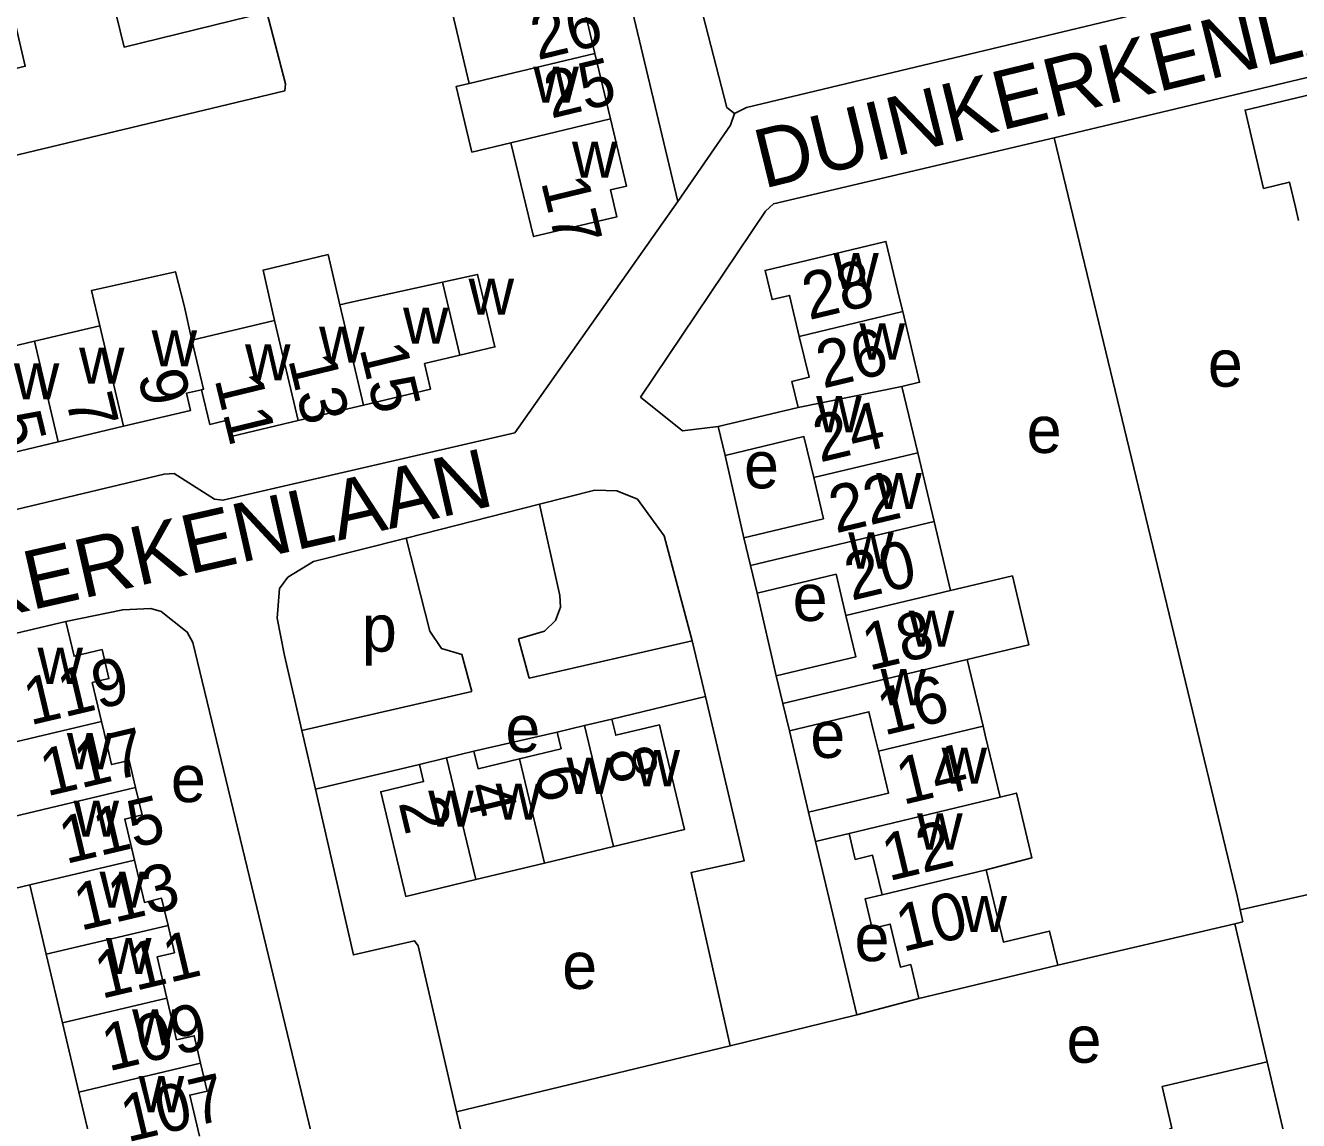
# Model space of a CAD drawing. Extents: x 157768 to 159790, y 387230 to 389604.
# Drawn here: x 159326.8 to 159435.1, y 388717.2 to 388810.4 of the extents above; entities that cross this region are included whole.
import ezdxf

# ---------------------------------------------------------------- set-up
doc = ezdxf.new("R2010")
doc.units = 0
for name, color, linetype in [('BLT_Basislijn', 7, 'Continuous'), ('BLT_Bebouwing', 7, 'Continuous'), ('BLT_Centroide', 7, 'Continuous'), ('BLT_Huisnummer', 7, 'Continuous'), ('BLT_Huisnummer_ tussenligend', 7, 'Continuous'), ('BLT_Onderverdeling_panden', 7, 'Continuous'), ('BLT_Straatnaam', 7, 'Continuous')]:
    doc.layers.add(name, color=color, linetype=linetype)

msp = doc.modelspace()

# ---------------------------------------------------------------- linework, layer by layer
at = {"layer": 'BLT_Basislijn'}
for p, q in [((159386.32, 388773.81), (159387.92, 388766.8)), ((159370.52, 388769.66), (159375.24, 388770.86)), ((159359.2, 388766.78), (159370.52, 388769.66)), ((159389.04, 388762.1), (159390.67, 388755.05)), ((159369.66, 388754.85), (159383.52, 388758.04)), ((159350.31, 388750.41), (159364.78, 388753.73)), ((159376.68, 388751.38), (159384.64, 388753.29)), ((159351.46, 388745.41), (159350.31, 388750.41)), ((159364.94, 388748.64), (159372.03, 388750.27)), ((159391.79, 388750.39), (159393.43, 388743.45)), ((159360.32, 388747.53), (159351.46, 388745.41)), ((159394.02, 388740.96), (159397.53, 388726.22)), ((159430.15, 388735.16), (159440.25, 388737.44)), ((159430.15, 388735.16), (159430.37, 388734.13)), ((159429.68, 388733.97), (159414.63, 388730.44)), ((159430.37, 388734.13), (159429.68, 388733.97)), ((159432.43, 388722.23), (159429.68, 388733.97)), ((159397.53, 388726.22), (159402.81, 388727.61)), ((159363.47, 388717.97), (159386.76, 388723.59))]:
    msp.add_line(p, q, dxfattribs=at)
for points in [[(159357.28, 388833.94), (159362.62, 388835.29), (159363.05, 388834.27), (159367.09, 388817.24), (159367.94, 388816.95), (159376.06, 388818.59), (159376.79, 388818.48), (159382.3, 388795.4)], [(159346.54, 388831.4), (159330.57, 388827.44), (159335.18, 388808.55), (159347.33, 388811.52), (159348.93, 388805.43), (159348.85, 388804.82), (159311.09, 388795.78), (159309.81, 388802.64), (159326.78, 388806.92), (159321.81, 388828.26)], [(159436.83, 388828.79), (159439.83, 388815.8), (159388.13, 388803.42), (159387.13, 388802.91)], [(159381.44, 388822.9), (159386.47, 388803.4), (159387.13, 388802.91)], [(159414.33, 388800.82), (159443.7, 388807.83), (159444.14, 388807.81), (159450.82, 388803.13), (159451.67, 388800.59), (159462.43, 388753.63), (159459.51, 388743.67), (159459.59, 388742.95)], [(159387.13, 388802.91), (159386.79, 388801.89), (159382.3, 388795.4)], [(159379.13, 388778.78), (159389.77, 388794.6), (159390.45, 388795.21), (159414.33, 388800.82)], [(159414.33, 388800.82), (159429.9, 388736.34), (159430.15, 388735.16)], [(159307.79, 388764.87), (159338.59, 388772.22), (159339.45, 388772.26), (159342.87, 388770.08), (159343.59, 388770), (159368.42, 388775.73), (159382.3, 388795.4)], [(159379.13, 388778.78), (159382.71, 388775.9), (159385.73, 388776.27)], [(159375.24, 388770.86), (159377.11, 388770.79), (159378.86, 388770.09), (159381.14, 388766.98), (159383.52, 388758.04)], [(159369.66, 388754.85), (159368.75, 388758.2), (159370.95, 388758.85), (159371.9, 388759.78), (159372.32, 388760.89), (159372.27, 388761.9), (159370.52, 388769.66)], [(159350.31, 388750.41), (159348.84, 388756.8), (159348.2, 388759.97), (159348.41, 388762.48), (159349.11, 388763.44), (159351.29, 388764.78), (159359.2, 388766.78)], [(159364.78, 388753.73), (159363.92, 388756.88), (159362.18, 388757.38), (159361.21, 388758.86), (159359.2, 388766.78)], [(159357.95, 388687.92), (159341.04, 388757.9), (159340.56, 388758.78), (159338.35, 388760.54), (159337.46, 388760.78), (159335.07, 388760.68), (159330.24, 388759.68)], [(159383.52, 388758.04), (159384.64, 388753.29)], [(159384.64, 388753.29), (159387.93, 388739.31), (159383.43, 388738.32), (159386.76, 388723.59)], [(159363.47, 388717.97), (159360.2, 388732.1), (159359.89, 388732.53), (159354.7, 388731.32), (159351.46, 388745.41)], [(159397.53, 388726.22), (159397.3, 388726.16), (159386.76, 388723.59)], [(159363.47, 388717.97), (159369.31, 388693.28), (159369.85, 388692.48), (159375.75, 388688.69), (159384.77, 388690.71)]]:
    msp.add_lwpolyline(points, dxfattribs=at)
at = {"layer": 'BLT_Bebouwing'}
for p, q in [((159376.57, 388802.43), (159375.25, 388807.99)), ((159340.96, 388783.62), (159347.99, 388785.29)), ((159327.57, 388783.53), (159333.12, 388784.84)), ((159322.02, 388782.21), (159327.57, 388783.53)), ((159401.36, 388779.67), (159402.71, 388774.03)), ((159350.01, 388776.77), (159355.57, 388778.09)), ((159392.54, 388777.9), (159385.73, 388776.27)), ((159329.59, 388774.97), (159335.14, 388776.29)), ((159385.73, 388776.27), (159386.32, 388773.81)), ((159324.04, 388773.65), (159329.59, 388774.97)), ((159402.71, 388774.03), (159404.11, 388768.19)), ((159404.11, 388768.19), (159405.51, 388762.32)), ((159387.92, 388766.8), (159388.48, 388764.45)), ((159388.48, 388764.45), (159389.04, 388762.1)), ((159323.23, 388758.02), (159330.24, 388759.68)), ((159406.92, 388756.45), (159408.27, 388750.78)), ((159390.67, 388755.05), (159391.23, 388752.72)), ((159391.23, 388752.72), (159391.79, 388750.39)), ((159374.36, 388750.83), (159372.03, 388750.27)), ((159376.68, 388751.38), (159374.36, 388750.83)), ((159364.94, 388748.64), (159362.63, 388748.09)), ((159362.63, 388748.09), (159360.32, 388747.53)), ((159393.43, 388743.45), (159394.02, 388740.96)), ((159394.02, 388740.96), (159396.88, 388741.65)), ((159370.96, 388739.13), (159376.82, 388740.53)), ((159365.11, 388737.73), (159370.96, 388739.13)), ((159327.17, 388737.28), (159328.57, 388731.37)), ((159328.57, 388731.37), (159329.95, 388725.53)), ((159329.95, 388725.53), (159331.34, 388719.65)), ((159331.34, 388719.65), (159332.72, 388713.79))]:
    msp.add_line(p, q, dxfattribs=at)
for points in [[(159375.25, 388807.99), (159373.42, 388815.68), (159362.74, 388813.14), (159364.56, 388805.45)], [(159364.56, 388805.45), (159363.43, 388805.18), (159364.78, 388799.62), (159368.09, 388800.41)], [(159443.96, 388795.9), (159443.13, 388799.41), (159444.59, 388799.76), (159444.01, 388802.23), (159439.7, 388801.21), (159438.76, 388805.14), (159430.56, 388803.19), (159432.14, 388796.52), (159434.34, 388797.05), (159434.85, 388794.92), (159435.11, 388793.8)], [(159368.09, 388800.41), (159370.03, 388792.42), (159377.1, 388794.1), (159376.56, 388796.39), (159377.93, 388796.71), (159376.57, 388802.43)], [(159401.43, 388786.04), (159401.17, 388787.15), (159400.01, 388792.01), (159389.72, 388789.55), (159390.32, 388787.06), (159391.8, 388787.42), (159392.63, 388783.94)], [(159347.99, 388785.29), (159347.01, 388789.57), (159352.55, 388790.89), (159353.55, 388786.61)], [(159333.12, 388784.84), (159332.42, 388787.84), (159339.55, 388789.44), (159340.3, 388786.55), (159340.96, 388783.62)], [(159353.55, 388786.61), (159354.38, 388786.81), (159362.28, 388788.55)], [(159362.28, 388788.55), (159365.26, 388789.21), (159366.73, 388783.04), (159363.76, 388782.33)], [(159401.43, 388786.04), (159402.87, 388780.03), (159401.36, 388779.67)], [(159392.63, 388783.94), (159393.46, 388780.46), (159392.01, 388780.11), (159392.54, 388777.9)], [(159363.76, 388782.33), (159360.76, 388781.62), (159361.27, 388779.45), (159355.57, 388778.09)], [(159335.14, 388776.29), (159340.84, 388777.64), (159340.49, 388779.1), (159341.77, 388779.4)], [(159341.77, 388779.4), (159342.47, 388776.45), (159343.97, 388776.81), (159344.3, 388775.42), (159350.01, 388776.77)], [(159386.32, 388773.81), (159393.02, 388775.41), (159393.86, 388771.92)], [(159393.86, 388771.92), (159394.69, 388768.42), (159387.92, 388766.8)], [(159389.04, 388762.1), (159395.76, 388763.7), (159396.6, 388760.18)], [(159405.51, 388762.32), (159410.76, 388763.56), (159412.15, 388757.69), (159406.92, 388756.45)], [(159330.24, 388759.68), (159330.93, 388756.72), (159333.31, 388757.29), (159333.9, 388754.83), (159332.48, 388754.49), (159333.26, 388751.18)], [(159396.6, 388760.18), (159397.44, 388756.67), (159390.67, 388755.05)], [(159391.79, 388750.39), (159398.56, 388752.01), (159399.04, 388750), (159399.37, 388748.65)], [(159333.26, 388751.18), (159333.48, 388750.25), (159334.13, 388747.51), (159335.62, 388747.86), (159336.17, 388745.55)], [(159376.82, 388740.53), (159382.86, 388741.98), (159380.94, 388750), (159380.73, 388750.89), (159377.02, 388750), (159376.68, 388751.38)], [(159408.27, 388750.78), (159408.46, 388750), (159409.71, 388744.75)], [(159372.03, 388750.27), (159372.37, 388748.86), (159368.83, 388748.01)], [(159368.83, 388748.01), (159365.3, 388747.16), (159364.94, 388748.64)], [(159399.37, 388748.65), (159400.22, 388745.07), (159393.43, 388743.45)], [(159360.32, 388747.53), (159360.67, 388746.07), (159357.02, 388745.2), (159359.15, 388736.3), (159365.11, 388737.73)], [(159336.06, 388739.39), (159335.24, 388742.88), (159336.72, 388743.23), (159336.17, 388745.55)], [(159409.71, 388744.75), (159411.11, 388745.08), (159412.42, 388739.58), (159408.53, 388738.55)], [(159325.8, 388743.09), (159325.87, 388742.8), (159321.92, 388741.87), (159323.22, 388736.34), (159327.17, 388737.28)], [(159396.88, 388741.65), (159397.4, 388739.44), (159398.87, 388739.8), (159399.67, 388736.43)], [(159338.93, 388733.82), (159338.38, 388736.14), (159336.91, 388735.79), (159336.06, 388739.39)], [(159408.53, 388738.55), (159410, 388732.41), (159413.93, 388733.35), (159414.63, 388730.44)], [(159399.67, 388736.43), (159398.23, 388736.09), (159398.83, 388733.58), (159400.36, 388733.94), (159401.24, 388730.29), (159402.12, 388730.5), (159402.81, 388727.61)], [(159338.82, 388727.63), (159337.99, 388731.15), (159339.47, 388731.5), (159338.93, 388733.82)], [(159402.81, 388727.61), (159414.63, 388730.44)], [(159341.7, 388722.1), (159341.15, 388724.45), (159339.65, 388724.1), (159338.82, 388727.63)], [(159341.6, 388715.89), (159340.77, 388719.39), (159342.26, 388719.74), (159341.7, 388722.1)], [(159424.14, 388716.53), (159424.32, 388716.57), (159423.52, 388720.14), (159432.43, 388722.23)], [(159432.43, 388722.23), (159433.96, 388715.71), (159435.1, 388710.84)]]:
    msp.add_lwpolyline(points, dxfattribs=at)
at = {"layer": 'BLT_Onderverdeling_panden'}
for p, q in [((159364.56, 388805.45), (159375.25, 388807.99)), ((159362.28, 388788.55), (159363.76, 388782.33)), ((159355.57, 388778.09), (159353.55, 388786.61)), ((159350.01, 388776.77), (159347.99, 388785.29)), ((159392.63, 388783.94), (159401.43, 388786.04)), ((159335.14, 388776.29), (159333.12, 388784.84)), ((159329.59, 388774.97), (159327.57, 388783.53)), ((159392.54, 388777.9), (159401.36, 388779.67)), ((159393.86, 388771.92), (159402.71, 388774.03)), ((159388.48, 388764.45), (159404.11, 388768.19)), ((159396.6, 388760.18), (159405.51, 388762.32)), ((159391.23, 388752.72), (159406.92, 388756.45)), ((159333.26, 388751.18), (159324.38, 388749.08)), ((159374.36, 388750.83), (159376.82, 388740.53)), ((159399.37, 388748.65), (159408.27, 388750.78)), ((159362.63, 388748.09), (159365.11, 388737.73)), ((159368.83, 388748.01), (159370.96, 388739.13)), ((159336.17, 388745.55), (159325.8, 388743.09)), ((159396.88, 388741.65), (159409.71, 388744.75)), ((159336.06, 388739.39), (159327.17, 388737.28)), ((159399.67, 388736.43), (159408.53, 388738.55)), ((159338.93, 388733.82), (159328.57, 388731.37)), ((159338.82, 388727.63), (159329.95, 388725.53)), ((159341.7, 388722.1), (159331.34, 388719.65))]:
    msp.add_line(p, q, dxfattribs=at)
for points in [[(159368.09, 388800.41), (159376.57, 388802.43)], [(159340.96, 388783.62), (159341.95, 388779.45), (159341.77, 388779.4)]]:
    msp.add_lwpolyline(points, dxfattribs=at)

# ---------------------------------------------------------------- texts
at = {"layer": 'BLT_Centroide'}
for s, p in [('w', (159370.01, 388803.81)), ('w', (159373.29, 388797.44)), ('w', (159395.53, 388787.97)), ('w', (159364.5, 388785.77)), ('w', (159358.92, 388783.31)), ('w', (159337.53, 388781.38)), ('w', (159351.78, 388781.69)), ('w', (159397.76, 388781.97)), ('w', (159331.36, 388779.91)), ('w', (159345.48, 388780.19)), ('e', (159427.39, 388779.66)), ('w', (159325.81, 388778.58)), ('w', (159394.07, 388775.78)), ('e', (159411.98, 388774.02)), ('e', (159387.93, 388771.01)), ('w', (159399.18, 388769.25)), ('w', (159396.8, 388764.19)), ('e', (159392.07, 388759.73)), ('p', (159355.42, 388757.12)), ('w', (159401.95, 388757.53)), ('w', (159327.82, 388754.38)), ('w', (159399.55, 388752.56)), ('e', (159367.63, 388748.57)), ('e', (159393.57, 388748.08)), ('w', (159330.32, 388747.12)), ('w', (159378.61, 388745.67)), ('w', (159404.74, 388745.88)), ('e', (159339.17, 388744.32)), ('w', (159372.83, 388745.02)), ('w', (159361.06, 388742.23)), ('w', (159366.8, 388742.83)), ('w', (159330.89, 388741.38)), ('w', (159402.66, 388740.28)), ('w', (159333.1, 388735.34)), ('w', (159406.44, 388733.27)), ('e', (159397.33, 388730.79)), ('w', (159333.65, 388729.69)), ('e', (159372.46, 388728.43)), ('w', (159335.87, 388723.62)), ('e', (159415.37, 388722.15)), ('w', (159336.43, 388717.94))]:
    msp.add_text(s, height=4, dxfattribs=at).set_placement(p)
at = {"layer": 'BLT_Huisnummer'}
for s, rotation, p in [('26', 13.6437, (159370.36, 388807.42)), ('25', 13.6437, (159371.51, 388802.45)), ('17', 283.6421, (159370.64, 388797.09)), ('28', 13.4717, (159393.45, 388785.31)), ('15', 283.6711, (159355.2, 388782.92)), ('9', 283.6711, (159336.32, 388780.63)), ('5', 283.6711, (159324.08, 388777.09)), ('22', 13.4717, (159395.73, 388767.17)), ('18', 13.4717, (159398.55, 388755.48)), ('119', 13.2999, (159327.19, 388750.84)), ('8', 283.4652, (159376.18, 388748.57)), ('14', 13.4717, (159401.44, 388744.07)), ('115', 13.2999, (159330.21, 388739.04)), ('2', 283.4638, (159358.52, 388744.28)), ('10', 13.4717, (159401.42, 388731.56)), ('111', 13.2999, (159333.25, 388727.57)), ('107', 13.2999, (159335.45, 388715.37))]:
    msp.add_text(s, height=4, rotation=rotation, dxfattribs=at).set_placement(p)
at = {"layer": 'BLT_Huisnummer_ tussenligend'}
for s, rotation, p in [('26', 13.4717, (159394.65, 388779.49)), ('13', 283.6711, (159349.13, 388781.98)), ('11', 283.6711, (159342.87, 388780.3)), ('7', 283.6711, (159330.2, 388778.6)), ('24', 13.4717, (159394.38, 388773.2)), ('20', 13.4717, (159397.06, 388761.44)), ('16', 13.4717, (159399.83, 388749.97)), ('117', 13.2999, (159328.59, 388744.79)), ('6', 283.4638, (159370.04, 388746.97)), ('4', 283.4638, (159364.15, 388745.63)), ('12', 13.4717, (159400.23, 388737.58)), ('113', 13.2999, (159331.47, 388733.36)), ('109', 13.2999, (159333.85, 388721.4))]:
    msp.add_text(s, height=4, rotation=rotation, dxfattribs=at).set_placement(p)
at = {"layer": 'BLT_Straatnaam'}
for rotation, p in [(13.7558, (159389.58, 388796.49)), (12.7558, (159307.02, 388756.05))]:
    msp.add_text('DUINKERKENLAAN', height=5, rotation=rotation, dxfattribs=at).set_placement(p)

doc.saveas('drawing.dxf')
